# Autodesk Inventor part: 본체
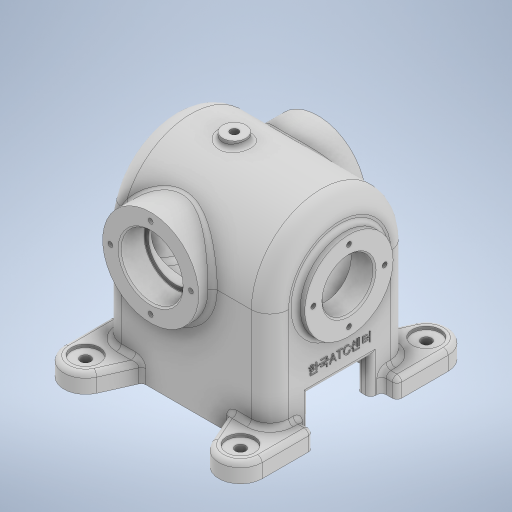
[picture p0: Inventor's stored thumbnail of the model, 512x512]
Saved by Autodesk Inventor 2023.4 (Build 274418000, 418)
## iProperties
Created: 2024-09
Part Number: 본체
Material: 일반
Document SubType Name: Modeling
Designer: EDU
Density: 1 g/cm^3
Appearance: 기본값
Author: EDU
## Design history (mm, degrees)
sketch "스케치1"
  geometry: L1 (0, 45)-(-76, 45); L2 (0, -45)-(-76, -45); L3 (-76, 45)-(-76, -45); A1 r 45 centre (0, 0) between (0, 45) and (0, -45); 1 further point
  constraints: 6 end point, 2 horizontal, 2 point on circle, 2 tangent, 1 centre point, 1 coincident, 1 vertical
  dimensions: "d0" = 90 diameter of A1; "d1" = 76 distance of L1.start L1.end
extrude "돌출1" new body sketch "스케치1" distance "d2" = 108; taper "d3" = 0 deg
feature "쉘1" dims "d4" = 9
sketch "스케치2"
  geometry: C1 r 45 at (0, 0); C2 r 36 at (0, 0); A1 r 45 centre (0, 0) between (45, 0) and (-45, 0) reference; 3 further points
  constraints: 2 centre point, 1 coincident
  dimensions: "d5" = 90 diameter of C1; "d6" = 9 radial gap between concentric circles of C1 C2
extrude "돌출2" join sketch "스케치2" distance "d7" = 108; taper "d8" = 0 deg
sketch "스케치3"
  geometry: L1 (-45, 0)-(-45, -76) reference; L2 (-45, -76)-(45, -76) reference; L3 (45, -76)-(45, 0) reference; L4 (-45, -76)-(45, -76) reference; L5 (20, -53)-(-20, -53); L6 (-20, -53)-(-20, -76); L7 (-20, -76)-(20, -76); L8 (20, -76)-(20, -53); A1 r 45 centre (0, 0) between (45, 0) and (-45, 0) reference; 7 further points
  constraints: 8 end point, 4 midpoint, 2 parallel, 1 coincident, 1 horizontal, 1 perpendicular, 1 point on line, 1 vertical alignment
  dimensions: "d9" = 23 distance between parallel lines of L2 L5; "d10" = 40 distance between parallel lines of L6 L8
extrude "돌출3" cut sketch "스케치3" distance "d11" = 108; taper "d12" = 0 deg
sketch "스케치4"
  geometry: L1 (-20, -76)-(-20, -53) reference; L2 (-20, -53)-(20, -53) reference; L3 (20, -53)-(20, -76) reference; L4 (20, -76)-(45, -76) reference; L5 (45, -76)-(45, 0) reference; L6 (-45, 0)-(-45, -76) reference; L7 (-45, -76)-(-20, -76) reference; C1 r 28.5 at (0, 0); A1 r 45 centre (0, 0) between (45, 0) and (-45, 0) reference; 1 further point
  constraints: 1 centre point, 1 coincident
  dimensions: "d13" = 57 diameter of C1
extrude "돌출4" join sketch "스케치4" distance "d14" = 6; taper "d15" = 0 deg
sketch "스케치5"
  geometry: C1 r 28.5 at (0, 0) reference; C2 r 16.5 at (0, 0); 1 further point
  constraints: 1 centre point, 1 coincident
  dimensions: "d16" = 33 diameter of C2
extrude "돌출5" cut sketch "스케치5" distance "d17" = 15; taper "d18" = 0 deg
chamfer "모따기1" distance "d19" = 1; stored, may be unused: second distance "d20" = 2, angle "d21" = 45 deg
sketch "스케치6"
  geometry: L1 (0, 76)-(0, 0) reference; L2 (0, 0)-(108, 0) reference; L3 (108, 76)-(108, 0) reference; L4 (0, 76)-(108, 76) reference; L5 (0, 76)-(108, 76) reference; L6 (114, 47.5)-(114, 104.5) reference; C1 r 31 at (40, 76); 1 further point
  constraints: 1 centre point, 1 midpoint, 1 point on line
  dimensions: "d22" = 62 diameter of C1; "d23" = 74 distance of point (114, 76) C1.centre
extrude "돌출6" join sketch "스케치6" distance "d24" = 9; taper "d25" = 0 deg
sketch "스케치7"
  geometry: L1 (-9, 76)-(-71, 76) reference; A1 r 31 centre (-40, 76) between (-9, 76) and (-71, 76) reference; 1 further point
extrude "돌출7" join sketch "스케치7" stored distance "d26" = 9; taper "d27" = 0 deg
sketch "스케치8"
  geometry: L1 (-31, 0)-(31, 0) reference; A1 r 31 centre (0, 0) between (31, 0) and (-31, 0) reference; 1 further point
extrude "돌출8" join sketch "스케치8" stored distance "d28" = 10; taper "d29" = 0 deg
sketch "스케치9"
  geometry: C1 r 31 at (0, 0) reference; C2 r 17.5 at (0, 0); 1 further point
  constraints: 1 centre point, 1 coincident
  dimensions: "d30" = 35 diameter of C2
extrude "돌출9" cut sketch "스케치9" extent not by distance; stored distance "d31" = 0; taper "d32" = 0 deg
sketch "스케치10"
  geometry: C1 r 17.5 at (0, 0) reference; C2 r 31 at (0, 0) reference; C3 r 20 at (0, 0); 1 further point
  constraints: 1 centre point, 1 coincident
  dimensions: "d33" = 40 diameter of C3
extrude "돌출10" cut sketch "스케치10" distance "d34" = 16; taper "d35" = 0 deg
chamfer "모따기2" distance "d36" = 1; stored, may be unused: second distance "d37" = 2, angle "d38" = 45 deg
chamfer "모따기3" distance "d39" = 1; stored, may be unused: second distance "d40" = 2, angle "d41" = 45 deg
fillet "모깎기1" dims "d42" = 0.3
sketch "스케치11"
  geometry: L1 (0, -25)-(9, -25) reference; L2 (9, -25)-(9, -9) reference; L3 (9, -9)-(99, -9) reference; L4 (99, -9)-(99, -25) reference; L5 (99, -25)-(108, -25) reference; L6 (108, 0)-(108, -25) reference; L7 (0, 0)-(108, 0) reference; L8 (0, 0)-(0, -25) reference; L9 (9, -65)-(0, -65) reference; L10 (0, -65)-(0, -90) reference; L11 (0, -90)-(108, -90) reference; L12 (108, -65)-(108, -90) reference; L13 (108, -65)-(99, -65) reference; L14 (99, -65)-(99, -81) reference; L15 (99, -81)-(9, -81) reference; L16 (9, -81)-(9, -65) reference; L17 (0, -65)-(0, -25) reference; L18 (61, 9)-(19, 9) reference; L19 (-10, 15)-(-10, -18); L20 (-10, -18)-(0, -18); L21 (9, 9)-(9, 0) reference; L22 (71, 9)-(9, 9) reference; L23 (108, 0)-(108, -25) reference; L24 (118, 15)-(118, -18); L25 (118, -18)-(108, -18); L26 (16.79, 20.693)-(26, 0); L27 (0, 0)-(108, 0) reference; L28 (91.21, 20.693)-(82, 0); A1 r 14 centre (4, 15) between (-10, 15) and (16.79, 20.693); A2 r 14 centre (104, 15) between (118, 15) and (91.21, 20.693); 9 further points
  constraints: 12 end point, 4 midpoint, 4 point on circle, 4 point on line, 4 tangent, 3 horizontal alignment, 2 centre point, 2 vertical, 1 horizontal, 1 perpendicular
  dimensions: "d46" = 28 diameter of A1; "d47" = 28 diameter of A2; "d48" = 100 distance of A2.centre A1.centre; "d50" = 18 distance between parallel lines of L20 L7; "d51" = 10 distance of L19.end L20.end; "d54" = 60 vertical distance of point (0, -45) A1.centre; "d55" = 36 distance from line of L26.end L19; "d56" = 36 distance from line of L28.end L24
extrude "돌출11" join sketch "스케치11" distance "d57" = 12; taper "d58" = 0 deg
node "작업 평면1"
sketch "스케치12"
  geometry: L1 (105, 7.5)-(105, 64.5) reference; L2 (-9, 16)-(-9, 56) reference; L3 (62, 90)-(0, 90) reference; L4 (62, -18)-(0, -18) reference; C1 r 7.5 at (31, 36); 3 further points
  constraints: 2 midpoint, 1 centre point, 1 horizontal alignment
  dimensions: "d60" = 15 diameter of C1; "d61" = 74 distance of point (105, 36) C1.centre
extrude "돌출12" join sketch "스케치12" stored distance "d62" = 12; taper "d63" = 0 deg
sketch "스케치13"
  geometry: L1 (-40, -45)-(-40, 45) reference; L2 (-40, 45)-(-31, 45) reference; L3 (-40, 45)-(-40, -45) reference; L4 (-40, -45)-(-31, -45) reference; L5 (31, -45)-(68, -45) reference; L6 (68, 45)-(68, -45) reference; L7 (31, 45)-(68, 45) reference; L8 (-31, 54)-(31, 54) reference; C1 r 7.5 at (0, 0) reference; 5 further points
  constraints: 3 horizontal alignment, 2 midpoint, 1 coincident, 1 vertical alignment, 1 other
hole "구멍1" sketch "스케치13" at (0, 0) diameter "d64" = 5.1881; stored, may be unused: countersink angle "d68" = 90 deg, drill point angle "d70" = 118 deg; dims "d65" = 150, "d66" = 4, "d67" = 2, "d69" = 16
sketch "스케치14" dims "d71" = 46
  geometry: C1 r 28.5 at (0, 0) reference; C2 r 17.5 at (0, 0) reference; 6 further points
  constraints: 2 vertical alignment, 1 coincident, 7 other
  dimensions: "d74" = 360 deg dimension on C2.centre point (0, 23) (derived)
hole "구멍2" sketch "스케치14" at (0, 23), (-23, 0), (0, -23), (23, 0) diameter "d76" = 3.242; stored, may be unused: countersink angle "d80" = 90 deg, drill point angle "d82" = 118 deg; dims "d77" = 8, "d78" = 4, "d79" = 2, "d81" = 10
sketch "스케치15" dims "d83" = 52
  geometry: C1 r 31 at (0, 0) reference; C2 r 21 at (0, 0) reference; 6 further points
  constraints: 2 vertical alignment, 1 coincident, 7 other
  dimensions: "d86" = 360 deg dimension on C2.centre point (0, 26) (derived)
hole "구멍3" sketch "스케치15" at (0, 26), (-26, 0), (0, -26), (26, 0) diameter "d88" = 3.242; stored, may be unused: countersink angle "d92" = 90 deg, drill point angle "d94" = 118 deg; dims "d89" = 8, "d90" = 4, "d91" = 2, "d93" = 10
fillet "모깎기2" dims "d95" = 12
fillet "모깎기3" dims "d96" = 3
sketch "스케치16"
  geometry: A1 r 14 centre (4, -15) between (-10, -15) and (16.79, -20.693) reference; 5 further points
  constraints: 2 horizontal alignment, 2 vertical alignment, 1 coincident
  dimensions: "d97" = 100 distance of point (104, -15) point (4, -15); "d98" = 120 distance of point (4, 105) point (4, -15)
hole "구멍4" sketch "스케치16" at (4, -15), (104, -15), (4, 105), (104, 105) diameter "d99" = 6.6; stored, may be unused: countersink angle "d103" = 82 deg, drill point angle "d105" = 0 deg; dims "d100" = 8, "d101" = 18, "d102" = 2, "d104" = 12
sketch "스케치17"
  geometry: L1 (-20, -53)-(20, -53) reference; L2 (-20.763, -37.998)-(20.763, -37.998); L3 (20.763, -37.998)-(20.763, -44.002); L4 (20.763, -44.002)-(-20.763, -44.002); L5 (-20.763, -44.002)-(-20.763, -37.998); L6 (-27, -76)-(-60, -76) reference; C1 r 33 at (0, 0) reference; 3 further points
  constraints: 2 midpoint, 1 vertical alignment, 2 other
  dimensions: "d106" = 35 distance from line of L6 point (-20.763, -41)
feature "엠보싱1" sketch "스케치17" dims "d107" = 0.5, "d108" = 0
fillet "모깎기4" dims "d109" = 3
fillet "모깎기5" dims "d110" = 3
fillet "모깎기6" dims "d111" = 3
fillet "모깎기7" dims "d112" = 3
fillet "모깎기8" dims "d113" = 3
feature "ݺ耀ݼ耀ݾ耀ހ耀ނ耀ބ耀ކ耀ވ耀" dims "d0" = 90, "d1" = 76, "d2" = 108, "d3" = 0, "d4" = 9, "d5" = 90, "d6" = 9, "d7" = 108, "d8" = 0, "d9" = 23, "d10" = 40, "d11" = 108, "d12" = 0, "d13" = 57, "d14" = 6, "d15" = 0, "d16" = 33, "d17" = 15, "d18" = 0, "d19" = 1, "d20" = 2, "d21" = 45 deg, "d22" = 62, "d23" = 74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
node "솔리드1"
mirror "미러1"
mirror "미러2"
mirror "미러3"
mirror "미러4"
mirror "미러5"
node "투영된 루프1"
node "투영된 루프2"
node "투영된 루프3"
node "투영된 루프4"
node "투영된 루프5"
node "투영된 루프6"
node "투영된 루프7"
node "투영된 루프8"
node "투영된 루프9"
node "투영된 루프10"
node "투영된 루프11"
node "투영된 루프12"
node "투영된 루프13"
node "투영된 루프14"
feature "A9D066F2-1C7D-4E18-AEED-F7BC21143FA4" dims "d99" = 6.6, "d100" = 8, "d101" = 18, "d102" = 2, "d103" = 82 deg, "d104" = 12, "d105" = 0
